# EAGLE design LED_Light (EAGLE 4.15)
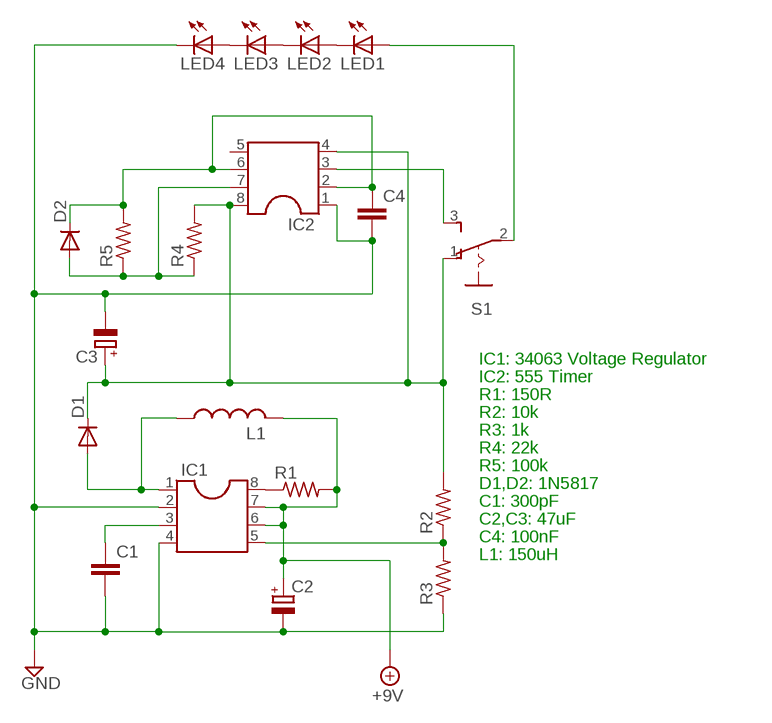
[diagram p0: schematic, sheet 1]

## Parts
C1  C-EU025-025X050  [C025-025X050]
C2  CPOL-EUE2.5-5  [E2,5-5]
C3  CPOL-EUE2.5-5  [E2,5-5]
C4  C-EU025-025X050  [C025-025X050]
D1  BAS15  [DO34-7]
D2  BAS15  [DO34-7]
IC1  DIL8  [DIL08]
IC2  DIL8  [DIL08]
L1  L-US0204/5  [0204/5]
LED1  LED5MM  [LED5MM]
LED2  LED5MM  [LED5MM]
LED3  LED5MM  [LED5MM]
LED4  LED5MM  [LED5MM]
R1  R-US_0204/7  [0204/7]
R2  R-US_0204/7  [0204/7]
R3  R-US_0204/7  [0204/7]
R4  R-US_0204/7  [0204/7]
R5  R-US_0204/7  [0204/7]
S1  255SB  [255SB]

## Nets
+9V: C2.+ IC1.6 IC1.7 L1.2 R1.2
GND: C1.2 C2.- C3.- C4.2 IC1.2 IC1.4 IC2.1 LED4.K(C) R3.1
N$1: C1.1 IC1.3
N$2: D1.A IC1.1 L1.1
N$3: IC1.8 R1.1
N$4: C3.+ D1.C IC2.4 IC2.8 R2.2 R4.2 S1.1(O)
N$5: IC1.5 R2.1 R3.2
N$6: D2.A IC2.7 R4.1 R5.1
N$7: LED2.K(C) LED3.A
N$8: C4.1 D2.C IC2.2 IC2.6 R5.2
N$9: IC2.3 S1.3(S)
N$10: LED1.A S1.2(P)
N$11: LED1.K(C) LED2.A
N$12: LED3.K(C) LED4.A
Unconnected: IC2.5

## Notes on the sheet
- IC1: 34063 Voltage Regulator
- IC2: 555 Timer
- R1: 150R
- R2: 10k
- R3: 1k
- R4: 22k
- R5: 100k
- D1,D2: 1N5817
- C1: 300pF
- C2,C3: 47uF
- C4: 100nF
- L1: 150uH

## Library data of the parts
C1 C4 = rcl:C-EU: CAPACITOR, European symbol
C2 C3 = rcl:CPOL-EU: POLARIZED CAPACITOR, European symbol
D1 D2 = diode:BAS15: DIODE
IC1 IC2 = ic-package:DIL8: Dual In Line
L1 = rcl:L-US: INDUCTOR, American symbol
LED1-LED4 = led:LED: LED
R1-R5 = rcl:R-US_: RESISTOR, American symbol
S1 = switch:255SB: SLIDING SWITCH distributor Buerklin, 11G810

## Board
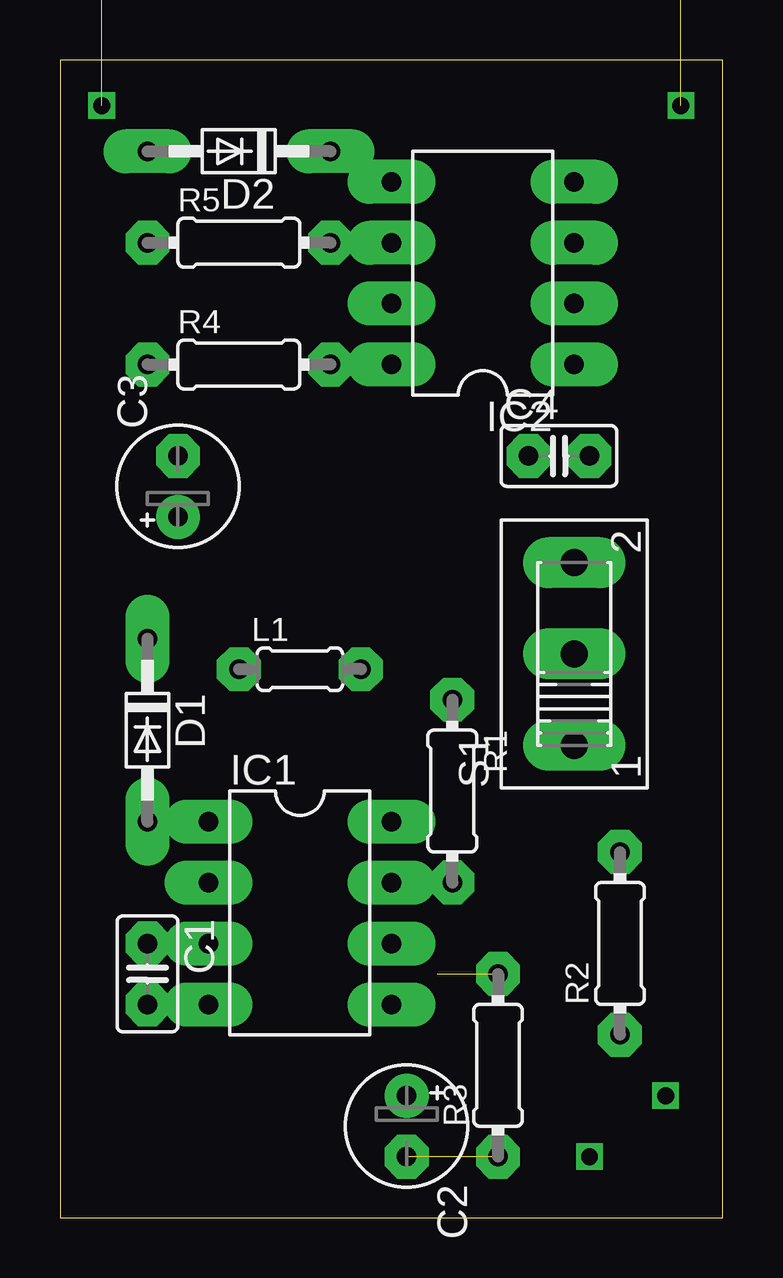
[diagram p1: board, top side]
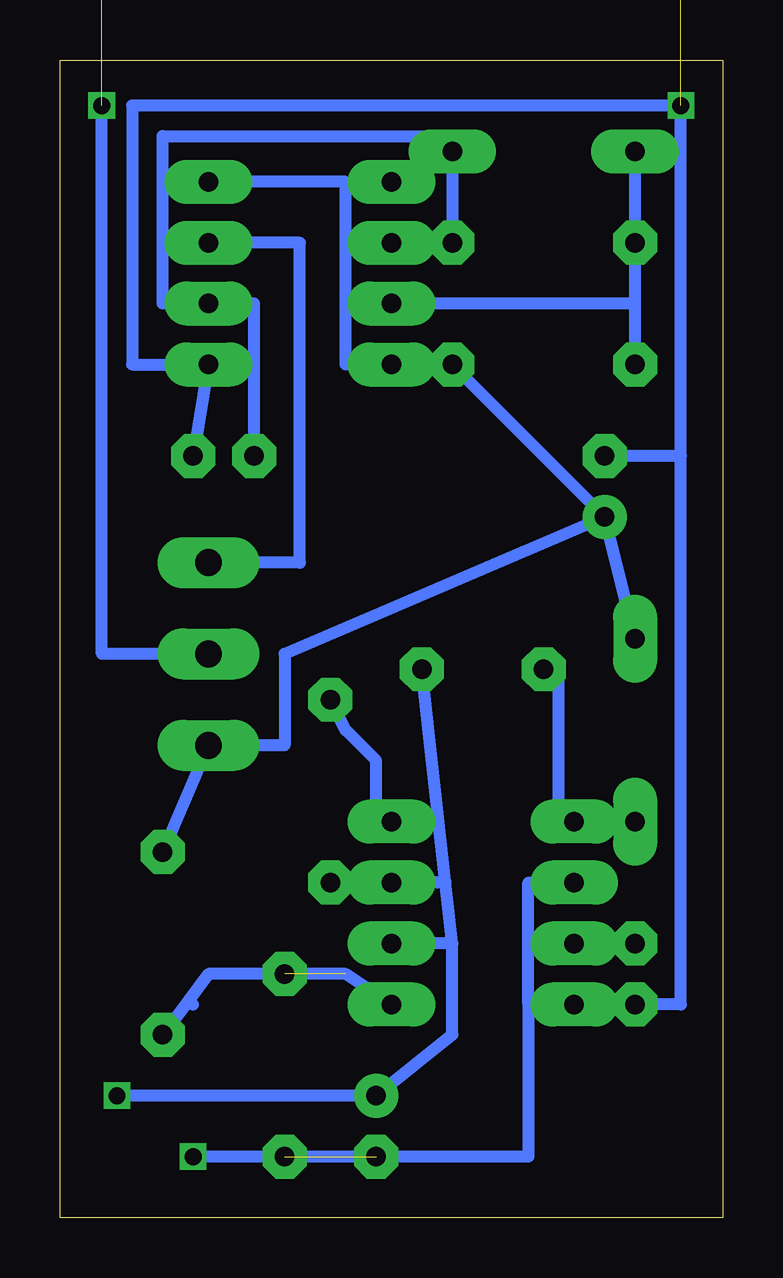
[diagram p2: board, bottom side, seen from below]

Size 27.61 x 48.25 mm. Coordinates in mm from the lower left corner, seen from the top.
Outline: 0,0 27.61,0 27.61,48.25 0,48.25 0,0
Copper layers (1*16): Top 0.035mm / dielectric 1.5mm / Bottom 0.035mm
Design rules "default": minimum track width 20mil, minimum drill 24mil, track to track 8mil, track to pad 8mil, pad to pad 8mil, via to via 8mil, smd to smd 0mil, copper to edge 40mil, drill to drill 8mil, minimum pad ring 20mil, minimum via ring 8mil, stop-mask expansion 4mil, vias tented up to drill 0mil, thermal gap 10mil
tKeepout: area 3,1.3 to 15.7,6.3; area 5.4,18.3 to 14.6,27.4; area 3.6,27.9 to 16.3,33

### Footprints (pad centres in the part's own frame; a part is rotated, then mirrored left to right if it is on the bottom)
C025-025X050 = drill 0.813 octagon: 1 -1.27,0; 2 1.27,0
E2,5-5 = drill 0.813 pad 1.6 round: + -1.27,0 | drill 0.813 pad 1.6 octagon: - 1.27,0
DO34-7 = drill 0.813 long: A 3.81,0; C -3.81,0
DIL08 = drill 0.813 long: 1 -3.81,-3.81; 2 -1.27,-3.81; 3 1.27,-3.81; 4 3.81,-3.81; 5 3.81,3.81; 6 1.27,3.81; 7 -1.27,3.81; 8 -3.81,3.81
0204/5 = drill 0.813 octagon: 1 -2.54,0; 2 2.54,0
LED5MM = drill 0.813 octagon: A -1.27,0; K 1.27,0
0204/7 = drill 0.813 octagon: 1 -3.81,0; 2 3.81,0
255SB = drill 1.118 long: 1 -3.81,0; 2 0,0; 3 3.81,0

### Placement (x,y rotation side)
C1  3.65,10.15 270 top
C2  14.44,3.81 270 top
C3  4.92,30.48 90 top
C4  20.79,31.75 0 top
D1  3.65,20.32 270 top
D2  7.46,44.45 180 top
IC1  10,12.69 270 top
IC2  17.62,39.36 90 top
L1  10,22.86 0 top
LED1  not placed on the board
LED2  not placed on the board
LED3  not placed on the board
LED4  not placed on the board
R1  16.35,17.78 270 top
R2  23.33,11.42 90 top
R3  18.25,6.34 90 top
R4  7.46,35.55 0 top
R5  7.46,40.63 0 top
S1  21.43,23.49 90 top

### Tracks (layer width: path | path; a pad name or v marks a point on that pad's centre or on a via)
+9V
  Bottom 0.508: 11.27,11.42 11.55,14 | 11.55,14 L1.2 | 11.27,11.42 11.27,7.62 C2.+ 25.23,5.08 | 11.27,11.42 IC1.6 | 11.55,14 11.9,13.96 IC1.7 R1.2
GND  (via drill 0.7)  (2 unrouted)
  Bottom 0.508: C4.2 IC2.1 24.6,35.55 24.6,46.35 v1.74,46.35 1.74,31.75 | 8.09,8.88 IC1.4 C1.2 1.74,8.88 1.74,31.75 | 1.74,31.75 C3.- | 22.06,2.54 C2.- 8.09,2.54 8.09,8.88 | IC1.2 8.09,13.96 8.09,8.88
N$1
  Bottom 0.508: C1.1 IC1.3
N$2
  Bottom 0.508: D1.A IC1.1 6.82,16.51 6.82,22.86 L1.1
N$3
  Bottom 0.508: R1.1 15.71,20.32 14.44,19.05 14.44,16.51 IC1.8
N$4
  Bottom 0.508: R2.2 S1.1 18.25,19.68 18.25,23.49 C3.+ | 13.17,35.55 R4.2 C3.+ | 13.17,35.55 IC2.8 | D1.C C3.+ | IC2.4 15.71,43.17 15.71,35.55 13.17,35.55
N$5  (1 unrouted)
  Bottom 0.508: 22.26,9.04 21.43,10.15 15.71,10.15 IC1.5 | 22.26,9.04 R2.1 | 22.26,9.04 22.06,8.88
N$6
  Bottom 0.508: 3.65,38.09 R5.1 D2.A | R4.1 3.65,38.09 | 3.65,38.09 IC2.7
N$7  (1 unrouted)
N$8
  Bottom 0.508: IC2.6 R5.2 D2.C 11.9,45.08 23.33,45.08 23.33,38.09 IC2.2 19.52,38.09 C4.1
N$9
  Bottom 0.508: IC2.3 17.62,40.63 17.62,27.3 S1.3
N$10  (1 unrouted)
  Bottom 0.508: S1.2 25.87,23.49 25.87,46.35
N$11  (1 unrouted)
N$12  (1 unrouted)
N$13  (via drill 0.7)
  other vias: 25.23,5.08
N$14  (via drill 0.7)
  other vias: 22.06,2.54
N$15  (via drill 0.7)
  other vias: 25.87,46.35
